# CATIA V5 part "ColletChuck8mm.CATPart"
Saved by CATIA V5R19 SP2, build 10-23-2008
Part number: ColletChuck8mm
Revision: ANY
Definition: UNKNOWN
Nomenclature: ColletChuck8mm
Source: Unknown
Bounding box of the stored display mesh (mm): x 0 to 9, y -7 to 7, z -7 to 6.989
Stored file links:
  Z:\fausse table rondelle-20220905T211342Z-001\fausse table rondelle\ColletChuck8mm.CATPart
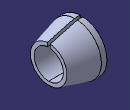
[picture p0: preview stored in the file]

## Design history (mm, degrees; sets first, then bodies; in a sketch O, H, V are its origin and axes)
AxisSystem1: origin (0, 0, 0), X (1, 0, 0), Y (0, 1, 0), Z (0, 0, 1)
Body1 "Schnitt-Linear austragen1" (main body)
  Solid1: solid without history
